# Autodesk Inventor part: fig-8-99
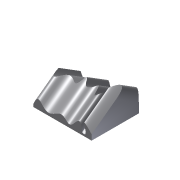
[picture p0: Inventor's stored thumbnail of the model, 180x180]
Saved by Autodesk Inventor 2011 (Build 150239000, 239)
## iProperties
Shininess: 64.0
Length Units: 11269
Angle Units: 11279
Time Units: 11290
Mass Units: 11283
Length Display Precision: 3
Angle Display Precision: 2
Compacted: True
Part Number: fig-8-99
Document SubType Name: Modeling
Created: 2002-12
Designer: deepak
Density: 1 g/cm^3
Density: 0.0
Volumn: 0.0
Area: 0.0
PropertySet Name: Model Information
Control State: 0
Master: False
Checked Out: False
Author: deepak
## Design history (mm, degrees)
sketch "Sketch1"
  geometry: L1 (-33.715, 26.527)-(30.916, 26.527); L2 (30.916, 26.527)-(30.916, -25.891); L3 (30.916, -25.891)-(-33.715, -25.891); L4 (-33.715, -25.891)-(-33.715, 26.527)
  constraints: 8 end point, 2 parallel, 1 horizontal, 1 perpendicular
extrude "Extrusion1" new body sketch "Sketch1" distance "d0" = 20; taper "d1" = 0 deg
sketch "Sketch2"
  geometry: L1 (-44.187, -5.757)-(15.849, 38.63)
  constraints: 2 end point
workplane "Work Plane1"
sketch "Sketch3"
  geometry: L1 (33.715, -6.248)-(33.715, 9.834) reference; L2 (-30.916, -6.248)-(-30.916, 9.834) reference; 10 further points
  constraints: 2 point on line, 11 other
feature "SweepSrf1" sketch "Sketch3" dims "d2" = 0
sketch "Sketch4"
  geometry: L1 (-26.819, 39.395)-(38.245, -1.181)
  constraints: 2 end point
workplane "Work Plane2"
sketch "Sketch5"
  geometry: L1 (-30.916, -5.198)-(-30.916, 11.772) reference; L2 (33.715, -5.198)-(33.715, 11.772) reference; 10 further points
  constraints: 2 point on line, 10 other
feature "SweepSrf2" sketch "Sketch5" dims "d3" = 0
feature "Replace Face4"
body "Solid1"
body "Srf1"
body "Srf2"
